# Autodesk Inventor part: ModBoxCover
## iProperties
Company: Autodes, Inc
Created: 2005-03
Part Number: ModBoxCover
Document SubType Name: Modeling
Density: 1 g/cm^3
Author: Admin
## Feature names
1. Extrusion1
2. Extrusion2
3. Fillet1
